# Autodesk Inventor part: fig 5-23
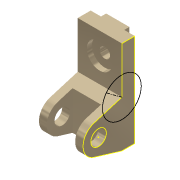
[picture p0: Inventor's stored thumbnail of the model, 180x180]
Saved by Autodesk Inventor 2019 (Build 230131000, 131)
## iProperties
Shininess: 65.0
Angle Display Precision: 2
Document Length Units: 11269
Document Angle Units: 11279
Document Time Units: 11290
Document Mass Units: 11283
Document Length Units Precision: 3
Document Angle Units Precision: 2
Compacted: False
Created: 2001-11
Part Number: fig 5-23
Document SubType Name: Modeling
Designer: Renu Muthoo
Density: 1 g/cm^3
Material: Generic
Appearance: Metal-Titanium (Polished)
Density: 0.0
Volumn: 0.0
Area: 0.0
PropertySet Name: Model Information
Control State: 0
Master: False
Checked Out: False
Author: Renu Muthoo
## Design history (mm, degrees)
node "Sketch1"
sketch "Sketch2"
  geometry: L1 (33.257, 104.664)-(33.257, -75.336); L2 (33.257, -75.336)-(8.257, -75.336); L3 (8.257, -75.336)-(-45.451, -59.045); L4 (-45.451, -1.628)-(8.257, 14.664); L5 (8.257, 14.664)-(8.257, 104.664); L6 (8.257, 104.664)-(33.257, 104.664); C1 r 15 at (-36.743, -30.336); A1 r 30 centre (-36.743, -30.336) between (-45.451, -1.628) and (-45.451, -59.045)
  constraints: 12 end point, 2 centre point, 2 equal length, 2 parallel, 2 point on circle, 2 tangent, 1 coincident, 1 perpendicular, 1 vertical
  dimensions: "d0" = 180 distance of L1.start L1.end; "d1" = 30 radius of A1; "d2" = 25 distance of L5.end L1.start; "d3" = 45 distance from line of L2 A1.centre; "d4" = 70 distance from line of L1 A1.centre; "d5" = 30 diameter of C1
extrude "Extrusion1" new body sketch "Sketch2" distance "d6" = 85; taper "d7" = 0 deg
workplane "Work Plane1"
sketch "Sketch3"
  geometry: L1 (15, 62.364)-(70, 62.364); L2 (70, 62.364)-(70, -52.386); L3 (70, -52.386)-(15, -52.386); L4 (15, -52.386)-(15, 62.364); L5 (0, -45)-(0, -28.708) reference
  constraints: 8 end point, 2 parallel, 1 horizontal, 1 perpendicular
  dimensions: "d8" = 55 distance of L1.start L1.end; "d9" = 15 distance between parallel lines of L5 L4
extrude "Extrusion2" cut sketch "Sketch3" distance "d10" = 50; taper "d11" = 0 deg
sketch "Sketch4"
  geometry: L1 (0, 25)-(85, 25) reference; L2 (0, 0)-(0, 25) reference; L3 (20, 25)-(65, 25); L4 (65, 25)-(65, 35); L5 (65, 35)-(20, 35); L6 (20, 35)-(20, 25)
  constraints: 8 end point, 2 parallel, 1 horizontal, 1 perpendicular, 1 point on line
  dimensions: "d12" = 45 distance of L4.end L5.end; "d13" = 10 distance of L3.end L4.end; "d14" = 20 distance between parallel lines of L2 L6
extrude "Extrusion3" join sketch "Sketch4" stored distance "d15" = 50; taper "d16" = 0 deg
sketch "Sketch5"
  geometry: L1 (85, 0)-(85, 90) reference; L2 (0, 90)-(85, 90) reference; 1 further point
  dimensions: "d17" = 42 distance from line of L2 point (42.5, 48); "d18" = 42.5 distance from line of L1 point (42.5, 48)
hole "Hole1" sketch "Sketch5" at (42.5, 48) diameter "d19" = 20; stored, may be unused: countersink angle "d23" = 82 deg, drill point angle "d25" = 118 deg; dims "d20" = 6, "d21" = 50, "d22" = 10, "d24" = 8
sketch "Sketch8"
  geometry: L1 (75.336, 33.257)-(75.336, 8.257) reference; L2 (-104.664, 33.257)-(75.336, 33.257) reference; L3 (-104.664, 8.257)-(-104.664, 33.257) reference; L4 (-14.664, 8.257)-(-104.664, 8.257) reference; L5 (1.628, -45.451)-(-14.664, 8.257) reference; L6 (75.336, 8.257)-(59.045, -45.451) reference; C1 r 15 at (30.336, -36.743) reference; C2 r 37.437 at (-14.664, 8.257); A1 r 30 centre (30.336, -36.743) between (1.628, -45.451) and (59.045, -45.451) reference
  constraints: 1 centre point, 1 coincident
sketch "Sketch9"
  geometry: L1 (75.336, 33.257)-(75.336, 8.257) reference; L2 (-14.664, 8.257)-(-104.664, 8.257) reference; L3 (1.628, -45.451)-(-14.664, 8.257) reference; L4 (75.336, 8.257)-(59.045, -45.451) reference; L5 (-14.664, 8.257)-(-37, -21.743); C1 r 15 at (30.336, -36.743) reference; A1 r 30 centre (30.336, -36.743) between (1.628, -45.451) and (59.045, -45.451) reference
  constraints: 2 end point
body "Solid1"
